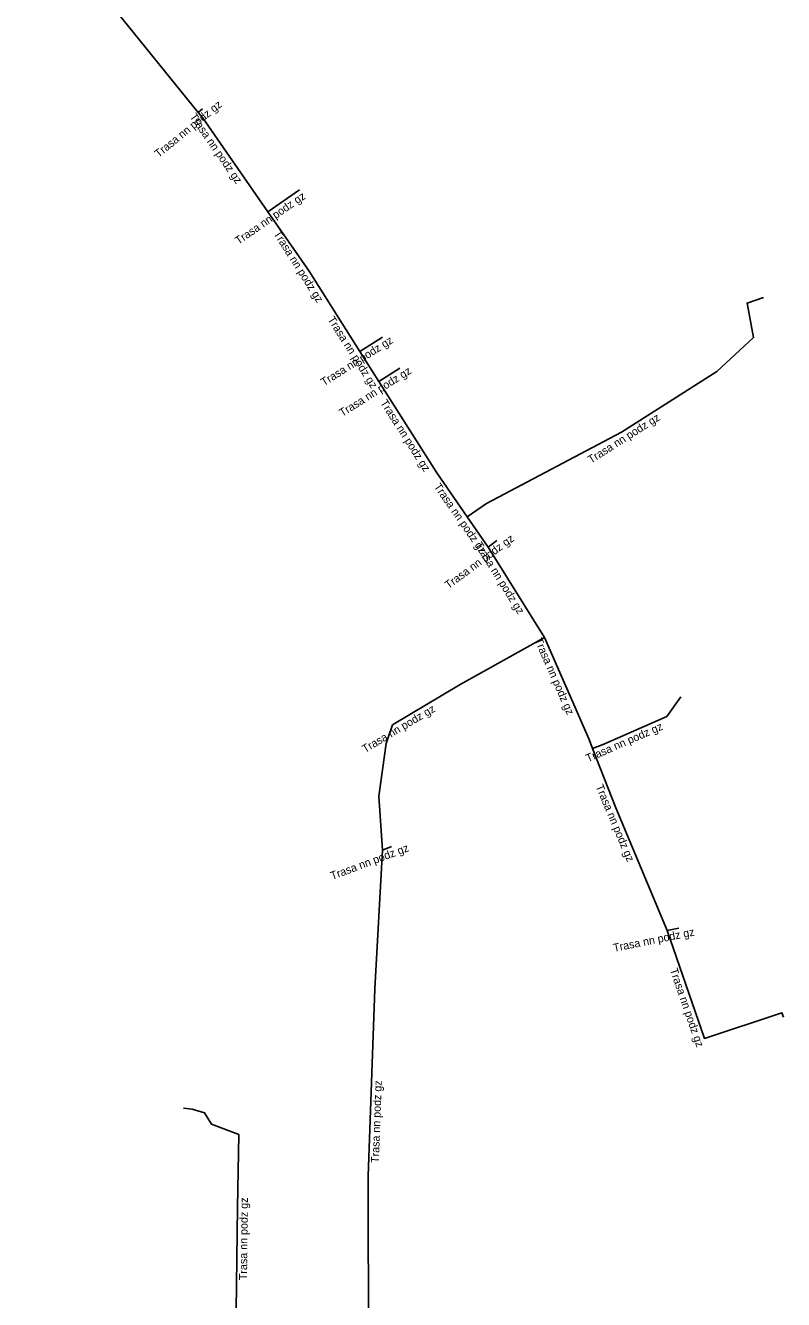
# Model space of a CAD drawing. Extents: x -660151 to -659156, y -1008082 to -1007440.
# Drawn here: x -659984.3 to -659936.9, y -1007663.7 to -1007584.1 of the extents above; entities that cross this region are included whole.
import ezdxf

# ---------------------------------------------------------------- set-up
doc = ezdxf.new("R2010")
doc.units = 0
doc.layers.add('Popiskový text - Ostatní atributy Trasy', color=7, linetype='Continuous')
doc.layers.add('Spojnice NN', color=7, linetype='Continuous')

msp = doc.modelspace()

# ---------------------------------------------------------------- linework, layer by layer
at = {"layer": 'Spojnice NN'}
for points in [[(-659973.51, -1007589.55), (-659978.91, -1007582.89), (-659984.3, -1007576.85), (-659984.23, -1007575.43), (-659983.31, -1007573.44), (-659981.6, -1007570.75)], [(-659973.51, -1007589.55), (-659973.24, -1007589.33)], [(-659969.15, -1007595.77), (-659973.24, -1007589.88), (-659973.51, -1007589.55)], [(-659969.15, -1007595.77), (-659967.17, -1007594.4)], [(-659963.41, -1007604.49), (-659966.58, -1007599.47), (-659969.15, -1007595.77)], [(-659956.71, -1007614.82), (-659955.49, -1007613.98), (-659947.06, -1007609.53), (-659941.11, -1007605.75), (-659938.81, -1007603.62), (-659939.22, -1007601.47), (-659938.2, -1007601.11)], [(-659963.41, -1007604.49), (-659962, -1007603.6)], [(-659962.22, -1007606.37), (-659963.41, -1007604.49)], [(-659962.22, -1007606.37), (-659960.91, -1007605.54)], [(-659956.71, -1007614.82), (-659958.6, -1007612.08), (-659962.22, -1007606.37)], [(-659955.4, -1007616.71), (-659956.71, -1007614.82)], [(-659955.4, -1007616.71), (-659954.86, -1007616.31)], [(-659951.87, -1007622.36), (-659955.4, -1007616.71)], [(-659962, -1007635.64), (-659962.23, -1007632.28), (-659961.76, -1007628.99), (-659961.38, -1007627.82), (-659957.14, -1007625.3), (-659951.87, -1007622.36)], [(-659951.87, -1007622.36), (-659949.09, -1007628.74), (-659948.87, -1007629.3)], [(-659948.87, -1007629.3), (-659948.16, -1007629.02), (-659944.24, -1007627.3), (-659943.36, -1007626.06)], [(-659948.87, -1007629.3), (-659947.42, -1007633.01), (-659944.21, -1007640.67)], [(-659962.86, -1007666.95), (-659962.9, -1007656.01), (-659962.48, -1007644.32), (-659962, -1007635.64)], [(-659962, -1007635.64), (-659961.44, -1007635.43)], [(-659944.21, -1007640.67), (-659943.47, -1007640.52)], [(-659944.21, -1007640.67), (-659941.88, -1007647.41), (-659937.04, -1007645.81), (-659936.94, -1007646.09)], [(-659972.27, -1007667.32), (-659971.72, -1007667.08), (-659971.15, -1007666.02), (-659971.06, -1007657.97), (-659970.98, -1007653.41), (-659972.67, -1007652.78), (-659973.11, -1007652.07), (-659973.88, -1007651.84), (-659974.43, -1007651.76)]]:
    msp.add_lwpolyline(points, dxfattribs=at)

# ---------------------------------------------------------------- texts
at = {"layer": 'Popiskový text - Ostatní atributy Trasy'}
for rotation, p in [(39.17366, (-659975.983, -1007592.403)), (304.77601, (-659974.071, -1007589.822)), (34.6801, (-659970.992, -1007597.835)), (302.27135, (-659968.826, -1007597.13)), (302.33294, (-659965.447, -1007602.488)), (32.26035, (-659965.65, -1007606.673)), (32.35785, (-659964.506, -1007608.588)), (302.3737, (-659962.153, -1007607.69)), (32.42756, (-659948.967, -1007611.512)), (304.72667, (-659958.808, -1007612.935)), (36.52886, (-659957.872, -1007619.35)), (301.99627, (-659956.249, -1007616.577)), (293.54452, (-659952.512, -1007622.516)), (30.72469, (-659963.086, -1007629.59)), (23.69069, (-659949.158, -1007630.167)), (292.73661, (-659948.689, -1007631.663)), (20.55605, (-659965.138, -1007637.511)), (11.45875, (-659947.527, -1007642.006)), (289.07013, (-659944.05, -1007643.122)), (87.94235, (-659962.221, -1007655.202)), (89.35945, (-659970.461, -1007662.518))]:
    msp.add_text('Trasa nn podz gz', height=0.5, rotation=rotation, dxfattribs=at).set_placement(p)

doc.saveas('drawing.dxf')
